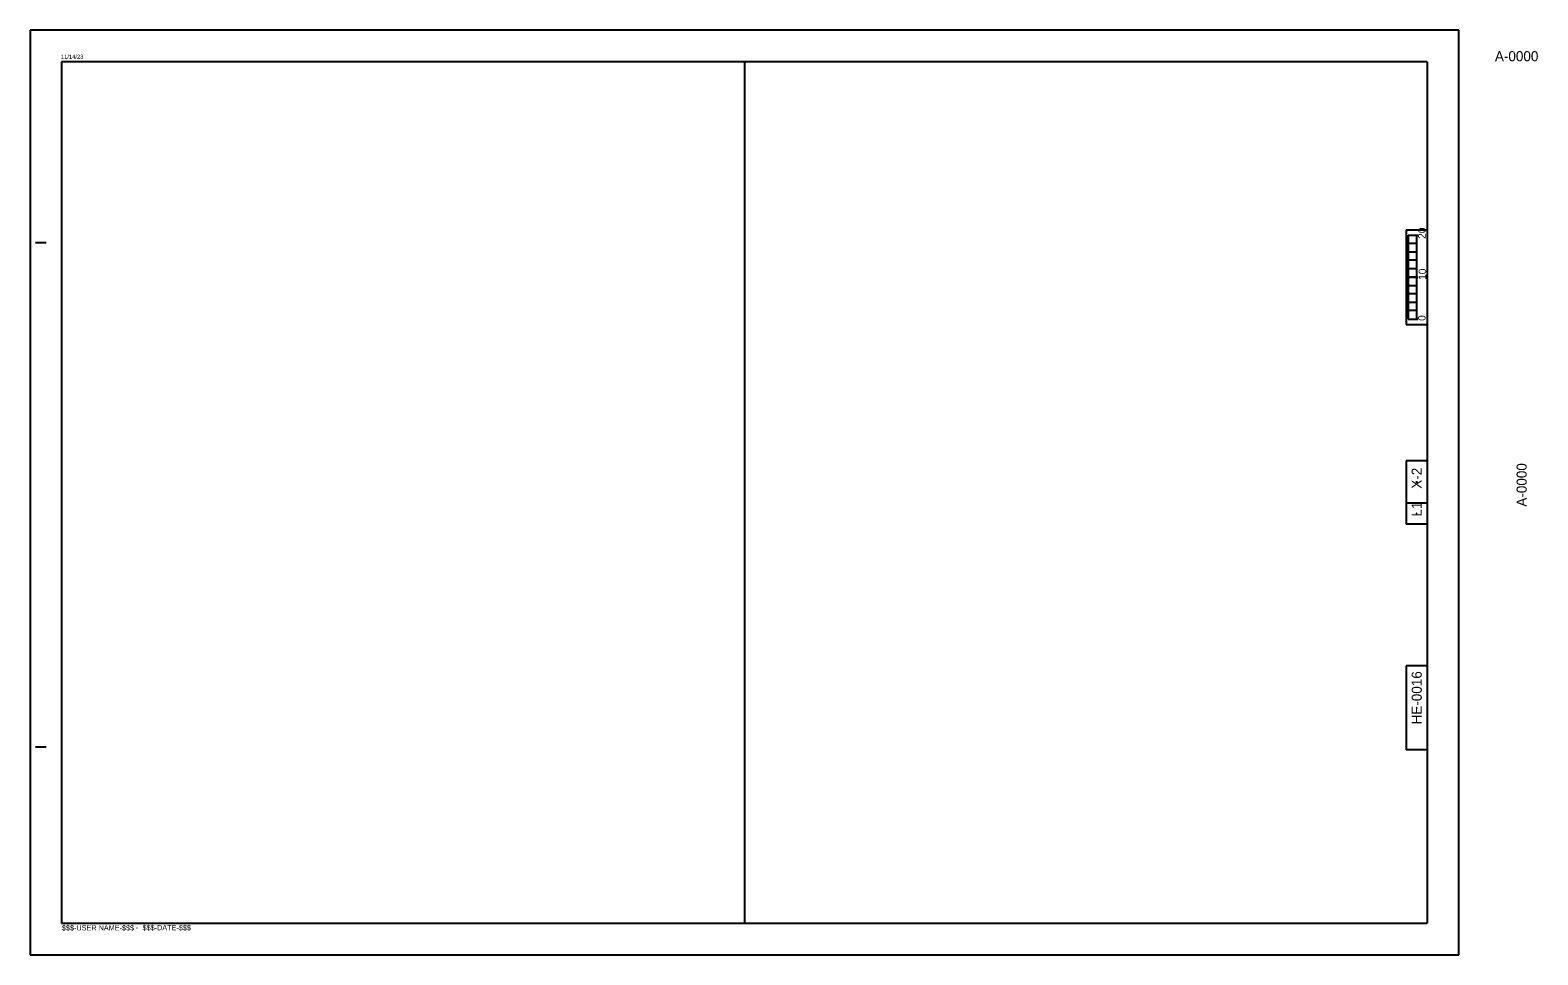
# Model space of a CAD drawing. Extents: x -2.69 to 2.99, y 0 to 1.83.
# Drawn here: x 0 to 2.99, y 0 to 1.833 of the extents above; entities that cross this region are included whole.
import ezdxf

# ---------------------------------------------------------------- set-up
doc = ezdxf.new("R2010")
doc.units = 0
for name, color, linetype in [('P_NCDOT_XS_Sheet_Alignment_Station_Label', 7, 'Continuous'), ('P_NCDOT_XS_Sheet_Grid_Border', 7, 'Continuous'), ('Sheet_Grid_Major', 7, 'Continuous'), ('Sheet_Grid_Middle', 7, 'Continuous'), ('Sheet_Grid_Minor', 7, 'Continuous')]:
    doc.layers.add(name, color=color, linetype=linetype)

msp = doc.modelspace()

# ---------------------------------------------------------------- linework, layer by layer
at = {"layer": 'P_NCDOT_XS_Sheet_Alignment_Station_Label'}
for p, q in [((2.7332, 1.4272), (2.7521, 1.4272)), ((2.7332, 1.4272), (2.7332, 1.2605)), ((2.7416, 1.4272), (2.7503, 1.4272)), ((2.7499, 1.4272), (2.7499, 1.2605)), ((2.7332, 1.3438), (2.7521, 1.3438)), ((2.7332, 1.2605), (2.7521, 1.2605)), ((2.7416, 1.2605), (2.7503, 1.2605))]:
    msp.add_line(p, q, dxfattribs=at)
for points in [[(2.7332, 1.4272), (2.7499, 1.4272), (2.7499, 1.4105), (2.7332, 1.4105)], [(2.7332, 1.3938), (2.7499, 1.3938), (2.7499, 1.3772), (2.7332, 1.3772)], [(2.7332, 1.3605), (2.7499, 1.3605), (2.7499, 1.3438), (2.7332, 1.3438)], [(2.7332, 1.3272), (2.7499, 1.3272), (2.7499, 1.3105), (2.7332, 1.3105)], [(2.7332, 1.2938), (2.7499, 1.2938), (2.7499, 1.2772), (2.7332, 1.2772)]]:
    msp.add_lwpolyline(points, close=True, dxfattribs=at)
at = {"layer": 'Sheet_Grid_Major'}
for p, q in [((2.8333, 1.8333), (0, 1.8333)), ((0, 1.8333), (0, 0)), ((2.8333, 0), (2.8333, 1.8333)), ((1.4167, 1.7708), (1.4166, 0.0625)), ((0, 0), (2.8333, 0))]:
    msp.add_line(p, q, dxfattribs=at)
for centre in [(2.7499, 1.3437), (2.7499, 0.9375), (2.7499, 0.875), (2.75, 0.4897)]:
    msp.add_circle(centre, 0.0001, dxfattribs=at)
at = {"layer": 'Sheet_Grid_Minor'}
for p, q in [((0.0625, 1.7708), (0.0625, 0.0625)), ((2.7708, 1.7708), (0.0625, 1.7708)), ((0.1027, 1.7844), (0.1027, 1.7844)), ((2.7708, 1.7708), (2.7708, 0.0625)), ((2.7292, 1.4375), (2.7292, 1.25)), ((2.7292, 1.4375), (2.7708, 1.4375)), ((0.0108, 1.4125), (0.0317, 1.4126)), ((2.7292, 1.25), (2.7708, 1.25)), ((2.7292, 0.9792), (2.7292, 0.8542)), ((2.7708, 0.9792), (2.7292, 0.9792)), ((2.7708, 0.8958), (2.7292, 0.8958)), ((2.7708, 0.8542), (2.7292, 0.8542)), ((2.7292, 0.5729), (2.7292, 0.4062)), ((2.7708, 0.5729), (2.7292, 0.5729)), ((0.0109, 0.4125), (0.0317, 0.4125)), ((2.7708, 0.4062), (2.7292, 0.4062)), ((0.0625, 0.0625), (2.7708, 0.0625))]:
    msp.add_line(p, q, dxfattribs=at)

# ---------------------------------------------------------------- texts
at = {"layer": 'P_NCDOT_XS_Sheet_Alignment_Station_Label'}
for s, p in [('20', (2.7678, 1.4196)), ('10', (2.7688, 1.3382)), ('0', (2.7677, 1.2569))]:
    msp.add_text(s, height=0.015, rotation=90, dxfattribs=at).set_placement(p)
at = {"layer": 'P_NCDOT_XS_Sheet_Grid_Border'}
for s, p in [('X-2', (2.7599, 0.9241)), ('L1', (2.7599, 0.8689))]:
    msp.add_text(s, height=0.02, rotation=90, dxfattribs=at).set_placement(p)
at = {"layer": 'Sheet_Grid_Middle'}
msp.add_text('A-0000', height=0.02, dxfattribs=at).set_placement((2.9051, 1.7717))
for s, p in [('A-0000', (2.9681, 0.8886)), ('HE-0016', (2.76, 0.4568))]:
    msp.add_text(s, height=0.02, rotation=90, dxfattribs=at).set_placement(p)
at = {"layer": 'Sheet_Grid_Minor'}
msp.add_text('11/14/23', height=0.00833, rotation=0, dxfattribs=at).set_placement((0.0609, 1.7764))
for s, height, p in [('$$$-DATE-$$$', 0.010417, (0.223, 0.0486)), ('$$$-USER NAME-$$$', 0.010417, (0.063, 0.0484)), ('-', 0.0104, (0.2093, 0.0494))]:
    msp.add_text(s, height=height, dxfattribs=at).set_placement(p)

doc.saveas('drawing.dxf')
